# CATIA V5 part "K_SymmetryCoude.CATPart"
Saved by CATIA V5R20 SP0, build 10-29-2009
Part number: Symmetry of Coude
Bounding box of the stored display mesh (mm): x 0 to 6, y -84.99 to 5, z -84.99 to 5.015
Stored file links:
  G:\Khaled_CFAO_2011\SIL\SIL_GR2\zthiebault\Khaled\CAD_ThinkMOTION\K_SymmetryCoude.CATPart
  G:\Khaled_CFAO_2011\SIL\SIL_GR2\zthiebault\Khaled\CAD_ThinkMOTION\K_Coude.CATPart
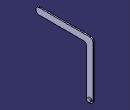
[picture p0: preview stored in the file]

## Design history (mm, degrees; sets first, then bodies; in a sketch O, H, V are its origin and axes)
Body1 (main body)
  Body2 "Corps du corps principal d'origine"
    Solid1: linked copy from another document
  Assemble1: tool Body2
